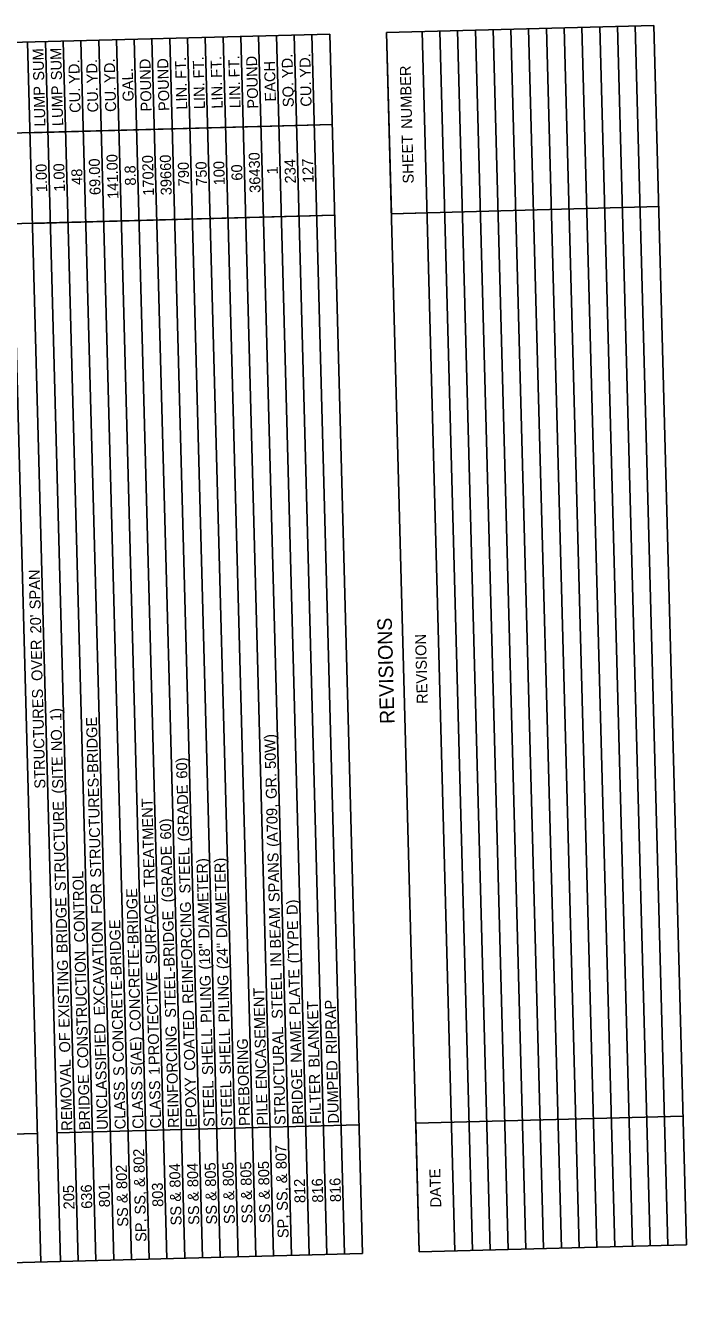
# Model space of a CAD drawing. Extents: x 1930078 to 1931323, y 596452 to 607874.
# Drawn here: x 1930714 to 1931077, y 606747 to 607442 of the extents above; entities that cross this region are included whole.
import ezdxf

# ---------------------------------------------------------------- set-up
doc = ezdxf.new("R2010")
doc.units = 0
doc.layers.add('Default', color=7, linetype='Continuous')

msp = doc.modelspace()

# ---------------------------------------------------------------- linework, layer by layer
at = {"layer": 'Default'}
for p, q in [((1931058.68, 607442.31), (1930912, 607438.38)), ((1931058.68, 607442.31), (1930912, 607438.38)), ((1930929.96, 606769.28), (1930912, 607438.38)), ((1930914.66, 607338.96), (1930912, 607438.38)), ((1930949.45, 606769.8), (1930931.49, 607438.9)), ((1930959.2, 606770.06), (1930941.24, 607439.16)), ((1930968.94, 606770.33), (1930950.98, 607439.42)), ((1930978.69, 606770.59), (1930960.73, 607439.68)), ((1930988.44, 606770.85), (1930970.47, 607439.95)), ((1930998.18, 606771.11), (1930980.22, 607440.21)), ((1931007.93, 606771.37), (1930989.97, 607440.47)), ((1931017.68, 606771.63), (1930999.71, 607440.73)), ((1931027.42, 606771.9), (1931009.46, 607440.99)), ((1931037.17, 606772.16), (1931019.21, 607441.25)), ((1931046.91, 606772.42), (1931028.95, 607441.52)), ((1931056.66, 606772.68), (1931038.7, 607441.78)), ((1931066.41, 606772.94), (1931048.45, 607442.04)), ((1931076.64, 606773.22), (1931058.68, 607442.31)), ((1930880.81, 607437.54), (1930080.62, 607416.06)), ((1930722.36, 606763.71), (1930704.4, 607432.8)), ((1930733.08, 606763.99), (1930715.12, 607433.09)), ((1930742.82, 606764.26), (1930724.86, 607433.35)), ((1930752.57, 606764.52), (1930734.61, 607433.61)), ((1930762.32, 606764.78), (1930744.36, 607433.88)), ((1930772.06, 606765.04), (1930754.1, 607434.14)), ((1930781.81, 606765.3), (1930763.85, 607434.4)), ((1930791.56, 606765.56), (1930773.6, 607434.66)), ((1930801.3, 606765.83), (1930783.34, 607434.92)), ((1930811.05, 606766.09), (1930793.09, 607435.18)), ((1930820.8, 606766.35), (1930802.83, 607435.45)), ((1930830.54, 606766.61), (1930812.58, 607435.71)), ((1930840.29, 606766.87), (1930822.33, 607435.97)), ((1930850.04, 606767.13), (1930832.07, 607436.23)), ((1930859.78, 606767.4), (1930841.82, 607436.49)), ((1930869.53, 606767.66), (1930851.57, 607436.75)), ((1930879.28, 606767.92), (1930861.31, 607437.02)), ((1930889.02, 606768.18), (1930871.06, 607437.28)), ((1930898.77, 606768.44), (1930880.81, 607437.54)), ((1930882.14, 607387.83), (1930081.95, 607366.35)), ((1930882.14, 607387.83), (1930716.45, 607383.38)), ((1931061.35, 607342.9), (1930914.66, 607338.96)), ((1930883.48, 607338.12), (1930083.29, 607316.64)), ((1930883.48, 607338.12), (1930717.79, 607333.68)), ((1930934.16, 607339.49), (1930914.66, 607338.96)), ((1931074.74, 606843.88), (1930928.06, 606839.94)), ((1930720.46, 606834.37), (1930096.68, 606817.62)), ((1930720.46, 606834.37), (1930125.92, 606818.41)), ((1930896.87, 606839.1), (1930731.18, 606834.66)), ((1930896.87, 606839.1), (1930731.18, 606834.66)), ((1930929.96, 606769.28), (1930928.06, 606839.94)), ((1931076.64, 606773.22), (1930929.96, 606769.28)), ((1931076.64, 606773.22), (1930929.96, 606769.28)), ((1930898.77, 606768.44), (1930098.58, 606746.96)), ((1930898.77, 606768.44), (1930098.58, 606746.96))]:
    msp.add_line(p, q, dxfattribs=at)

# ---------------------------------------------------------------- texts
for s, height, p in [(' SUM', 6, (1930724.3, 607409.77)), (' SUM', 6, (1930734.04, 607410.03)), (' FT.', 6, (1930812.04, 607411.06)), (' FT.', 6, (1930821.79, 607411.32)), (' FT.', 6, (1930831.54, 607411.58)), ('POUND', 6, (1930841.69, 607396.7)), (' YD.', 6, (1930860.81, 607411.2)), (' YD.', 6, (1930870.55, 607411.46)), (' YD.', 6, (1930743.85, 607408.06)), (' YD.', 6, (1930753.6, 607408.32)), (' YD.', 6, (1930763.34, 607408.58)), ('GAL.', 6, (1930773.31, 607400.59)), ('POUND', 6, (1930783.21, 607395.13)), ('POUND', 6, (1930792.96, 607395.39)), (' FT.', 6, (1930802.3, 607410.8)), ('EACH', 6, (1930851.34, 607400.56)), (' NUMBER', 6, (1930926.23, 607383.36)), ('LIN.', 6, (1930822.18, 607396.69)), ('LIN.', 6, (1930831.93, 607396.95)), ('SQ.', 6, (1930861.17, 607397.49)), ('CU.', 6, (1930870.92, 607397.76)), ('LUMP', 6, (1930724.91, 607386.85)), ('LUMP', 6, (1930734.66, 607387.11)), ('CU.', 6, (1930744.22, 607394.36)), ('CU.', 6, (1930753.96, 607394.62)), ('CU.', 6, (1930763.71, 607394.88)), ('LIN.', 6, (1930802.69, 607396.16)), ('LIN.', 6, (1930812.44, 607396.42)), ('SHEET', 6, (1930926.97, 607355.59)), ('69.00', 6, (1930755.18, 607349.27)), ('141.00', 6, (1930764.99, 607347.2)), ('17020', 6, (1930784.45, 607348.89)), ('39660', 6, (1930794.2, 607349.15)), ('36430', 6, (1930842.93, 607350.45)), ('1.00', 6, (1930725.88, 607350.81)), ('1.00', 6, (1930735.62, 607351.07)), ('48', 6, (1930745.28, 607354.81)), ('8.8', 6, (1930774.55, 607354.43)), ('790', 6, (1930803.82, 607354.07)), ('750', 6, (1930813.57, 607354.33)), ('100', 6, (1930823.31, 607354.59)), ('60', 6, (1930833, 607357.18)), ('1', 6, (1930852.41, 607360.6)), ('234', 6, (1930862.3, 607355.64)), ('127', 6, (1930872.04, 607355.89)), (' SPAN', 6, (1930722.33, 607119.75)), (" 20'", 6, (1930722.68, 607106.48)), ('REVISIONS', 8, (1930916.42, 607059.14)), (' OVER', 6, (1930723.38, 607080.44)), ('REVISION', 6, (1930934.64, 607070.1)), ('STRUCTURES', 6, (1930724.91, 607023.58)), (' 1)', 6, (1930733.73, 607058.42)), (' NO.', 6, (1930734.17, 607041.92)), (' STRUCTURES-BRIDGE', 6, (1930755.54, 606972.51)), (' 50W)', 6, (1930851.47, 607032.16)), (' (SITE', 6, (1930734.8, 607018.63)), (' 60)', 6, (1930802.85, 607026.84)), (' GR.', 6, (1930851.92, 607015.67)), (' (GRADE', 6, (1930803.78, 606992.37)), (' STRUCTURE', 6, (1930736.23, 606965.06)), (' TREATMENT', 6, (1930784.95, 606967.02)), (' (A709,', 6, (1930852.62, 606989.4)), (' 60)', 6, (1930793.99, 606993.4)), (' (GRADE', 6, (1930794.92, 606958.92)), (' STEEL', 6, (1930804.54, 606963.78)), (' SPANS', 6, (1930853.44, 606959.1)), (' DIAMETER)', 6, (1930814.96, 606939.08)), (' DIAMETER)', 6, (1930824.71, 606939.34)), (' CONTROL', 6, (1930746.74, 606936.96)), (' FOR', 6, (1930756.07, 606952.61)), (' CONCRETE-BRIDGE', 6, (1930777.31, 606888.33)), (' BRIDGE', 6, (1930737.15, 606931.05)), (' SURFACE', 6, (1930786.07, 606925.09)), (' REINFORCING', 6, (1930806.17, 606903.32)), (' D)', 6, (1930863.38, 606952.03)), (' STEEL-BRIDGE', 6, (1930796.62, 606895.57)), (' BEAM', 6, (1930854.12, 606933.65)), (' EXCAVATION', 6, (1930757.57, 606896.94)), (' CONCRETE-BRIDGE', 6, (1930768.01, 606871.17)), (' (TYPE', 6, (1930864.09, 606925.47)), (' (18"', 6, (1930815.42, 606922.07)), (' (24"', 6, (1930825.16, 606922.33)), (' CONSTRUCTION', 6, (1930748.6, 606867.81)), (' IN', 6, (1930854.39, 606923.63)), (' EXISTING', 6, (1930738.24, 606890.13)), (' PLATE', 6, (1930864.86, 606897.04)), (' PROTECTIVE', 6, (1930787.56, 606869.66)), (' PILING', 6, (1930816.2, 606892.79)), (' PILING', 6, (1930825.95, 606893.05)), (' STEEL', 6, (1930855.16, 606895.05)), (' ENCASEMENT', 6, (1930846.44, 606856.46)), (' BLANKET', 6, (1930875.38, 606868.28)), (' RIPRAP', 6, (1930884.94, 606875.66)), (' COATED', 6, (1930807.15, 606866.51)), (' NAME', 6, (1930865.56, 606870.95)), (' OF', 6, (1930738.61, 606876.55)), ('UNCLASSIFIED', 6, (1930759.19, 606836.38)), ('REINFORCING', 6, (1930798.18, 606837.43)), (' SHELL', 6, (1930816.97, 606864.21)), (' SHELL', 6, (1930826.72, 606864.47)), ('STRUCTURAL', 6, (1930856.66, 606839)), (' S(AE)', 6, (1930777.96, 606863.95)), ('PREBORING', 6, (1930837.17, 606838.48)), ('REMOVAL', 6, (1930739.7, 606835.86)), (' S', 6, (1930768.22, 606863.69)), (' 1', 6, (1930787.71, 606864.21)), ('BRIDGE', 6, (1930866.41, 606839.26)), ('DUMPED', 6, (1930885.9, 606839.79)), ('BRIDGE', 6, (1930749.45, 606836.12)), ('CLASS', 6, (1930768.94, 606836.65)), ('CLASS', 6, (1930778.69, 606836.91)), ('CLASS', 6, (1930788.43, 606837.17)), ('EPOXY', 6, (1930807.93, 606837.69)), ('STEEL', 6, (1930817.67, 606837.95)), ('STEEL', 6, (1930827.42, 606838.22)), ('FILTER', 6, (1930876.15, 606839.52)), ('PILE', 6, (1930846.91, 606838.74)), (' 807', 6, (1930857.37, 606812.52)), (' 802', 6, (1930779.4, 606810.46)), (' 802', 6, (1930769.88, 606801.65)), (' 804', 6, (1930799.12, 606802.41)), (' 804', 6, (1930808.87, 606802.67)), (' 805', 6, (1930818.61, 606802.9)), (' 805', 6, (1930828.36, 606803.16)), (' 805', 6, (1930838.11, 606803.42)), (' 805', 6, (1930847.85, 606803.68)), ('DATE', 6, (1930942.05, 606793.75)), ('205', 6, (1930740.86, 606792.73)), ('636', 6, (1930750.61, 606793.02)), ('801', 6, (1930760.34, 606793.86)), (' &', 6, (1930779.6, 606802.74)), ('803', 6, (1930789.59, 606794.07)), (' &', 6, (1930857.58, 606804.8)), ('812', 6, (1930867.56, 606796.19)), ('816', 6, (1930877.31, 606796.42)), ('816', 6, (1930887.06, 606796.68)), (' &', 6, (1930770.09, 606793.92)), (' SS,', 6, (1930780.01, 606787.65)), (' &', 6, (1930799.33, 606794.69)), (' &', 6, (1930809.07, 606794.95)), (' &', 6, (1930818.82, 606795.17)), (' &', 6, (1930828.57, 606795.43)), (' &', 6, (1930838.32, 606795.7)), (' &', 6, (1930848.06, 606795.96)), (' SS,', 6, (1930857.98, 606789.71)), ('SS', 6, (1930770.38, 606783.18)), ('SS', 6, (1930799.62, 606783.94)), ('SS', 6, (1930809.36, 606784.2)), ('SS', 6, (1930819.11, 606784.43)), ('SS', 6, (1930828.86, 606784.69)), ('SS', 6, (1930838.6, 606784.95)), ('SS', 6, (1930848.35, 606785.21)), ('SP,', 6, (1930780.35, 606774.88)), ('SP,', 6, (1930858.33, 606776.94))]:
    msp.add_text(s, height=height, rotation=91.53769, dxfattribs=at).set_placement(p)

doc.saveas('drawing.dxf')
